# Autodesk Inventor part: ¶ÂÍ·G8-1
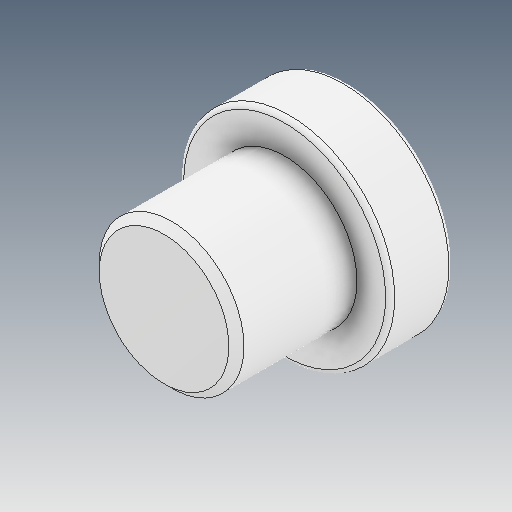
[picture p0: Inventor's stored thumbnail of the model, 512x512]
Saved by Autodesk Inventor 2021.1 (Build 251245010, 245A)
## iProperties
Created: 2021-05
Part Number: ¶ÂÍ·G8-1
Material: Ogólny
Document SubType Name: Modeling
Designer: user
Density: 1 g/cm^3
Appearance: Domyślna
Author: user
Revision Number: ÈÎºÎ
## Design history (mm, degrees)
feature "µ¹½Ç2"
node "Bryła1"
